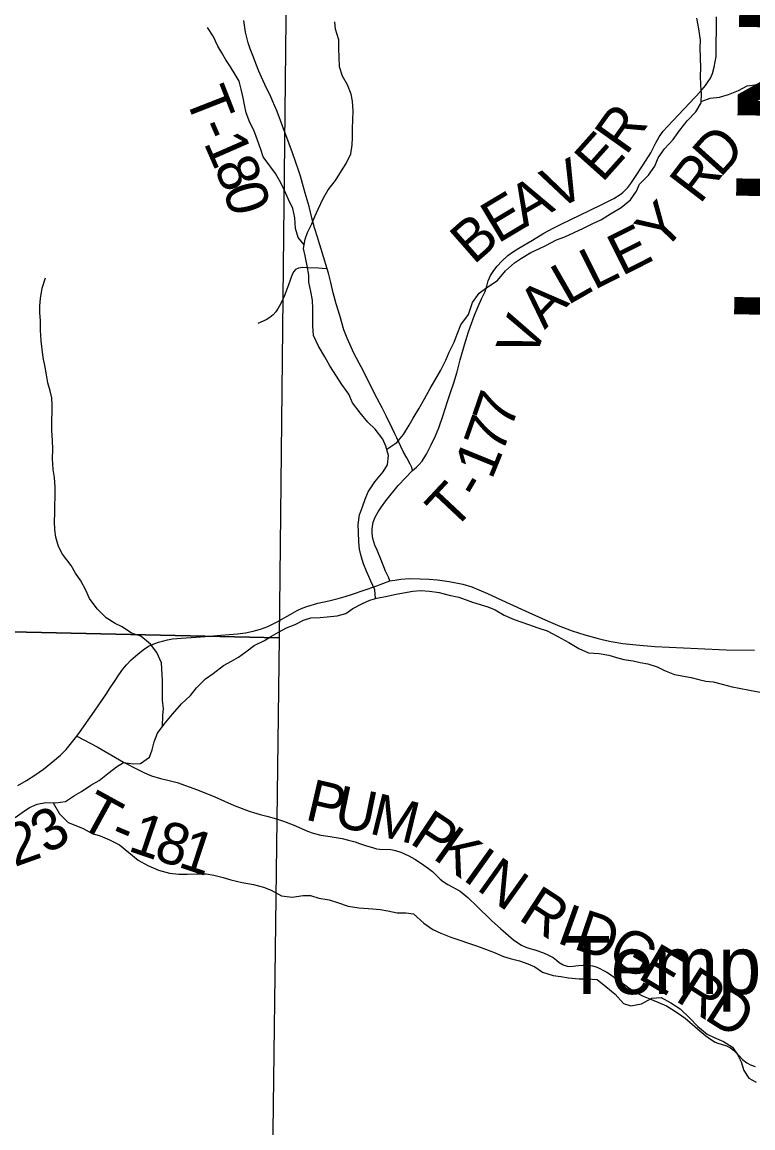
# Model space of a CAD drawing. Extents: x 0 to 191, y 0 to 55.
# Drawn here: x 148.858 to 149.356, y 23.231 to 23.985 of the extents above; entities that cross this region are included whole.
import ezdxf

# ---------------------------------------------------------------- set-up
doc = ezdxf.new("R2010")
doc.units = 0
for name, color, linetype in [('GM_X_Corporation', 7, 'Continuous'), ('GM_X_County_Road', 7, 'Continuous'), ('GM_X_County_Road_Text', 7, 'Continuous'), ('GM_X_County_Text', 7, 'Continuous'), ('GM_X_Minor_River', 7, 'Continuous'), ('GM_X_Township_Road', 7, 'Continuous'), ('GM_X_Township_Road_Text', 7, 'Continuous'), ('GM_X_Unincorporated_Text', 7, 'Continuous')]:
    doc.layers.add(name, color=color, linetype=linetype)

msp = doc.modelspace()

# ---------------------------------------------------------------- linework, layer by layer
at = {"layer": 'GM_X_Corporation'}
for points in [[(148.53297, 24.08032), (149.03882, 24.07143), (149.03316, 23.56525), (148.52633, 23.57659)], [(149.03316, 23.56525), (149.02664, 23.05167), (148.5174, 23.05975), (148.52633, 23.57659)]]:
    msp.add_lwpolyline(points, close=True, dxfattribs=at)
at = {"layer": 'GM_X_County_Road'}
msp.add_lwpolyline([(148.85501, 23.46471), (148.86079, 23.46796), (148.86656, 23.47163), (148.8724, 23.47584), (148.87997, 23.48191), (148.88406, 23.4854), (148.88803, 23.48925), (148.89525, 23.49815), (148.89711, 23.50086), (148.90722, 23.51529), (148.91522, 23.52696), (148.91792, 23.53111), (148.92141, 23.53628), (148.92388, 23.54007), (148.92664, 23.54386), (148.92905, 23.54681), (148.93236, 23.55036), (148.93681, 23.5542), (148.94054, 23.55721), (148.94421, 23.5595), (148.94854, 23.56148), (148.95094, 23.56226), (148.95371, 23.56305), (148.95702, 23.56383), (148.96057, 23.56449), (148.9664, 23.56509), (148.9732, 23.56557), (148.98601, 23.56647), (148.99352, 23.56708), (149.00489, 23.56804), (149.01024, 23.56876), (149.01554, 23.56984), (149.02047, 23.57129), (149.02558, 23.57309), (149.03196, 23.5761), (149.04074, 23.58115), (149.04555, 23.58392), (149.04898, 23.58542), (149.0521, 23.58674), (149.05962, 23.58897), (149.06714, 23.59053), (149.07346, 23.59203), (149.07839, 23.59342), (149.08336, 23.59496), (149.09926, 23.60058), (149.10872, 23.6041), (149.11213, 23.60467), (149.11628, 23.60527), (149.12253, 23.60581), (149.12945, 23.60557), (149.1354, 23.60527), (149.1413, 23.60479), (149.14924, 23.6037), (149.1585, 23.60196), (149.16463, 23.60003), (149.16944, 23.59805), (149.1754, 23.59546), (149.18821, 23.58969), (149.20361, 23.58253), (149.21684, 23.5767), (149.22478, 23.57321), (149.23326, 23.57002), (149.24174, 23.56732), (149.251, 23.56479), (149.25467, 23.56389), (149.25972, 23.56274), (149.26766, 23.56148), (149.27692, 23.56046), (149.28949, 23.55944), (149.31884, 23.55799), (149.33815, 23.55703), (149.35768, 23.55691)], dxfattribs=at)
at = {"layer": 'GM_X_Minor_River'}
for points in [[(149.16255, 23.78571), (149.16521, 23.79378), (149.16967, 23.80029), (149.17492, 23.80414), (149.18223, 23.80897), (149.18764, 23.81549), (149.19381, 23.82088), (149.19868, 23.82416), (149.20507, 23.82803), (149.21033, 23.83056), (149.21522, 23.83271), (149.22255, 23.83659), (149.22819, 23.83875), (149.23459, 23.84149), (149.24098, 23.8446), (149.24681, 23.84752), (149.2532, 23.85044), (149.25939, 23.85431), (149.26653, 23.85857), (149.27308, 23.86377), (149.27717, 23.8697), (149.27919, 23.87466), (149.28535, 23.88061), (149.28963, 23.88674), (149.29182, 23.89245), (149.2961, 23.89857), (149.30207, 23.90509), (149.30672, 23.91141), (149.31174, 23.91773), (149.31753, 23.92387), (149.32124, 23.92999), (149.32153, 23.93644), (149.3209, 23.94174), (149.32081, 23.94856), (149.32094, 23.9535), (149.32066, 23.96089), (149.32058, 23.96753), (149.3207, 23.97265), (149.31966, 23.98041), (149.31824, 23.98779)], [(149.05033, 23.83315), (149.04634, 23.83827), (149.04443, 23.84434), (149.04403, 23.85156), (149.04269, 23.85801), (149.03964, 23.86407), (149.03697, 23.87014), (149.0343, 23.87545), (149.03068, 23.88189), (149.02687, 23.88701), (149.02231, 23.89326), (149.02078, 23.89819), (149.01849, 23.90445), (149.016, 23.91128), (149.01333, 23.91658), (149.01085, 23.92322), (149.0097, 23.92854), (149.00874, 23.93347), (149.0074, 23.93935), (149.00606, 23.94466), (149.0032, 23.9494), (148.99996, 23.95452), (148.99691, 23.95926), (148.99425, 23.964), (148.99139, 23.96874), (148.98815, 23.97537), (148.98434, 23.98144)], [(149.09903, 23.592), (149.0985, 23.59811), (149.09583, 23.60399), (149.09278, 23.61081), (149.09087, 23.61574), (149.08915, 23.62086), (149.08819, 23.62579), (149.08761, 23.63072), (149.0874, 23.63737), (149.0872, 23.64249), (149.08814, 23.64914), (149.09002, 23.65465), (149.09191, 23.65978), (149.09398, 23.66472), (149.09852, 23.67157), (149.1042, 23.67842), (149.10722, 23.68318), (149.10778, 23.68963), (149.10605, 23.69589), (149.10396, 23.70063), (149.09882, 23.70764), (149.09387, 23.71237), (149.08855, 23.71862), (149.08322, 23.72543), (149.08074, 23.7315), (149.07598, 23.73794), (149.07236, 23.74362), (149.06779, 23.75063), (149.06437, 23.75689), (149.06017, 23.76409), (149.05674, 23.77129), (149.05616, 23.77793), (149.05633, 23.78439), (149.05632, 23.78951), (149.05593, 23.7954), (149.05478, 23.80128), (149.05362, 23.80773), (149.05361, 23.81248), (149.05246, 23.81893), (149.05111, 23.82576), (149.04996, 23.83069), (149.0509, 23.83696), (149.05259, 23.84171), (149.05562, 23.84761), (149.05769, 23.85255), (149.05977, 23.85749), (149.06335, 23.86472), (149.06676, 23.87062), (149.07167, 23.87709), (149.07583, 23.88355), (149.07905, 23.88869), (149.08226, 23.89516), (149.083, 23.90143), (149.08337, 23.90617), (149.08335, 23.91244), (149.08353, 23.91852), (149.0837, 23.9244), (149.08331, 23.93124), (149.08235, 23.93598), (149.07987, 23.94224), (149.07644, 23.94812), (149.07453, 23.95457), (149.07413, 23.9614), (149.07393, 23.96672), (149.07391, 23.97299), (149.07181, 23.98019), (149.07123, 23.98513)], [(149.32127, 23.93085), (149.32724, 23.93329), (149.33367, 23.93375), (149.33989, 23.93572), (149.34666, 23.93846), (149.35267, 23.94157), (149.35966, 23.94242)], [(148.95363, 23.50492), (148.95392, 23.51243), (148.9543, 23.51717), (148.95371, 23.52267), (148.95368, 23.53615), (148.9529, 23.5483), (148.94985, 23.55531), (148.94547, 23.56099), (148.93882, 23.56647), (148.93255, 23.56854), (148.92609, 23.5727), (148.92134, 23.57496), (148.91526, 23.57893), (148.90899, 23.58498), (148.90385, 23.59199), (148.90137, 23.59767), (148.89794, 23.60412), (148.89432, 23.60942), (148.89128, 23.61454), (148.88538, 23.6223), (148.88271, 23.62761), (148.8808, 23.63386), (148.88022, 23.63899), (148.88001, 23.64449), (148.88019, 23.65019), (148.88018, 23.65512), (148.88055, 23.66177), (148.88034, 23.66803), (148.87995, 23.67467), (148.87918, 23.67999), (148.87859, 23.6872), (148.87876, 23.69384), (148.87856, 23.69973), (148.87817, 23.70656), (148.87815, 23.71339), (148.87833, 23.71947), (148.87832, 23.72421), (148.87812, 23.72896), (148.87697, 23.7337), (148.87544, 23.73901), (148.87448, 23.74451), (148.87351, 23.74983), (148.87236, 23.75647), (148.87159, 23.76216), (148.87082, 23.76766), (148.87042, 23.77506), (148.87041, 23.78171), (148.87001, 23.78683), (148.87, 23.79158), (148.87037, 23.79652), (148.87168, 23.80374), (148.87375, 23.81077)], [(149.10662, 23.69384), (149.11345, 23.69838), (149.11818, 23.7039), (149.12196, 23.71018), (149.12479, 23.71493), (149.12857, 23.7214), (149.13254, 23.72825), (149.13632, 23.73528), (149.13953, 23.7408), (149.1435, 23.74783), (149.1469, 23.75449), (149.14936, 23.76), (149.15257, 23.76685), (149.15464, 23.77236), (149.15728, 23.77863), (149.16255, 23.78571)], [(148.97684, 23.53129), (148.98309, 23.53738), (148.9882, 23.54101), (148.99521, 23.54634), (149.00071, 23.5494), (149.00544, 23.55207), (149.01056, 23.55569), (149.01624, 23.56008), (149.02325, 23.56351), (149.02799, 23.56638), (149.03292, 23.56924), (149.03822, 23.5721), (149.0441, 23.5744), (149.04997, 23.57727), (149.0549, 23.57899), (149.06135, 23.5792), (149.06609, 23.5796), (149.07292, 23.58019), (149.0788, 23.58191), (149.08354, 23.58534), (149.09017, 23.58878), (149.0951, 23.59089), (149.09984, 23.59223), (149.10704, 23.59377), (149.11197, 23.59493), (149.11804, 23.59589), (149.12449, 23.59705), (149.1298, 23.59745), (149.13587, 23.59709), (149.14233, 23.59616), (149.14916, 23.59429), (149.1558, 23.59298), (149.16526, 23.58961)], [(149.16526, 23.58961), (149.17572, 23.58634), (149.18067, 23.58432), (149.18676, 23.5808), (149.1936, 23.57785), (149.19873, 23.57602), (149.20348, 23.57437), (149.20975, 23.57199), (149.21621, 23.56998), (149.22344, 23.56628), (149.23087, 23.56202), (149.23773, 23.55793), (149.24438, 23.55498), (149.25157, 23.55469), (149.25821, 23.55345), (149.26352, 23.55181), (149.26845, 23.55055), (149.27471, 23.54949), (149.27964, 23.54841), (149.28475, 23.54753), (149.29121, 23.54553), (149.29616, 23.54293), (149.303, 23.54037), (149.31437, 23.53824), (149.31968, 23.53679), (149.32442, 23.53571), (149.32935, 23.53539), (149.33561, 23.53376), (149.34244, 23.53177), (149.34718, 23.53088), (149.35419, 23.52964), (149.36139, 23.52821)], [(148.85315, 23.44283), (148.85788, 23.44626), (148.863, 23.44969), (148.86811, 23.45199), (148.87399, 23.45314), (148.88063, 23.45278), (148.88746, 23.45376), (148.89371, 23.45776), (148.89845, 23.46062), (148.9047, 23.46482), (148.91039, 23.46806), (148.91739, 23.47359), (148.92232, 23.4774), (148.92706, 23.48026), (148.93389, 23.47934), (148.93863, 23.47954), (148.94469, 23.48393), (148.94658, 23.48887), (148.94808, 23.49438), (148.95016, 23.50027), (148.9547, 23.50635), (148.96056, 23.51321), (148.96662, 23.52025), (148.97268, 23.52596), (148.97684, 23.53129)], [(148.87917, 23.45286), (148.8835, 23.44539), (148.8892, 23.43934), (148.89452, 23.43726), (148.89946, 23.43538), (148.90572, 23.4318), (148.91104, 23.4303), (148.9175, 23.42747), (148.92433, 23.42426), (148.93061, 23.41897), (148.93707, 23.41367), (148.94372, 23.41009), (148.95093, 23.40689), (148.95834, 23.40482), (148.96479, 23.40408), (148.97048, 23.4041), (148.97712, 23.40431), (148.98357, 23.40433), (148.9887, 23.40359), (148.99515, 23.4019), (149.00028, 23.4004), (149.00806, 23.39853), (149.01565, 23.39703), (149.02249, 23.39535), (149.0278, 23.39328), (149.03483, 23.38931), (149.04223, 23.38839), (149.04963, 23.38974), (149.05475, 23.38957), (149.06026, 23.38788), (149.06747, 23.38676), (149.07298, 23.38488), (149.08038, 23.38244), (149.08759, 23.38132), (149.09708, 23.38059), (149.10221, 23.38004), (149.10733, 23.3791), (149.11378, 23.3778), (149.11967, 23.37781), (149.12498, 23.37707), (149.13201, 23.37083), (149.13809, 23.36649), (149.1436, 23.36404), (149.15044, 23.36121), (149.16849, 23.3552)], [(149.16849, 23.3552), (149.17957, 23.35098), (149.18623, 23.34803), (149.19097, 23.34658), (149.19723, 23.34514), (149.20293, 23.34294), (149.20769, 23.34091), (149.21283, 23.33738), (149.22024, 23.33519), (149.22535, 23.33431), (149.23066, 23.33343), (149.23785, 23.33276), (149.24334, 23.33283), (149.25015, 23.33235), (149.25626, 23.32769), (149.26257, 23.32246), (149.26832, 23.3159), (149.27325, 23.31444), (149.28042, 23.31586), (149.28756, 23.31974), (149.29399, 23.32001), (149.30046, 23.31649), (149.30694, 23.3124), (149.31326, 23.30623), (149.31901, 23.30024), (149.32531, 23.29501), (149.33007, 23.2928), (149.33653, 23.29003), (149.34263, 23.28632), (149.34609, 23.28124), (149.34843, 23.27616), (149.35039, 23.27031), (149.35367, 23.26504), (149.35862, 23.26245)]]:
    msp.add_lwpolyline(points, dxfattribs=at)
at = {"layer": 'GM_X_Township_Road'}
for points in [[(149.10872, 23.6041), (149.1078, 23.60665), (149.10581, 23.6108), (149.10305, 23.61778), (149.1001, 23.62494), (149.09862, 23.62854), (149.09724, 23.63295), (149.09671, 23.6363), (149.09662, 23.63957), (149.09742, 23.64406), (149.09878, 23.64751), (149.10087, 23.65115), (149.10309, 23.65469), (149.10613, 23.65875), (149.11448, 23.66913), (149.1243, 23.67941), (149.12707, 23.68169), (149.12889, 23.68335), (149.13077, 23.68563), (149.13228, 23.68797), (149.13375, 23.69056), (149.13696, 23.69678), (149.13988, 23.70297), (149.14225, 23.70851), (149.1449, 23.71645), (149.14813, 23.72637), (149.14992, 23.73194), (149.15254, 23.73918), (149.15469, 23.74657), (149.15666, 23.75473), (149.15974, 23.76504), (149.16242, 23.77388), (149.16652, 23.78521), (149.16895, 23.79115), (149.17126, 23.79648), (149.17372, 23.80141), (149.17489, 23.80498), (149.17582, 23.80855), (149.17674, 23.81061), (149.17754, 23.81231), (149.1797, 23.81579), (149.18204, 23.81868), (149.18521, 23.82213), (149.1894, 23.82595), (149.19318, 23.82857), (149.19685, 23.831), (149.20602, 23.83639), (149.21387, 23.8411), (149.22028, 23.84464), (149.22567, 23.84732), (149.23842, 23.85335), (149.25298, 23.86053), (149.26154, 23.86478), (149.26594, 23.86758), (149.26785, 23.86897), (149.26936, 23.87035), (149.27118, 23.87232), (149.27315, 23.87491), (149.27589, 23.87916), (149.28155, 23.88775), (149.28685, 23.89597), (149.2903, 23.90284), (149.29255, 23.90678), (149.29532, 23.9106), (149.29834, 23.91392), (149.32066, 23.93766), (149.32405, 23.94173), (149.32608, 23.94453), (149.3275, 23.9469), (149.32885, 23.95007), (149.32999, 23.95423), (149.33134, 23.96168), (149.33173, 23.98861)], [(149.1243, 23.67941), (149.12372, 23.68141), (149.12255, 23.68372), (149.1203, 23.68794), (149.11814, 23.69179), (149.11629, 23.6958), (149.11498, 23.69875), (149.11352, 23.7017), (149.11227, 23.70432), (149.11031, 23.70829), (149.10646, 23.71627), (149.10351, 23.72205), (149.10024, 23.7284), (149.09556, 23.7373), (149.09163, 23.7452), (149.08912, 23.74997), (149.08778, 23.75262), (149.08415, 23.75944), (149.07962, 23.76951), (149.07745, 23.77529), (149.07456, 23.78503), (149.07223, 23.79289), (149.07021, 23.80049), (149.06851, 23.80749), (149.06684, 23.81393), (149.06612, 23.81682), (149.0635, 23.82507), (149.05933, 23.83839), (149.05737, 23.84482), (149.05546, 23.85155), (149.05364, 23.8593), (149.05111, 23.86833), (149.04792, 23.88001), (149.04646, 23.88421), (149.04235, 23.896), (149.04, 23.90211), (149.0358, 23.9137), (149.0318, 23.9241), (149.02865, 23.93146), (149.02704, 23.93518), (149.02474, 23.93995), (149.02123, 23.94742), (149.0195, 23.95154), (149.01733, 23.95684), (149.01578, 23.96107), (149.01357, 23.9667), (149.01208, 23.97099), (149.01114, 23.97444), (149.01041, 23.97817), (149.00925, 23.98606)], [(149.06612, 23.81682), (149.0627, 23.81715), (149.06008, 23.81723), (149.05295, 23.81755), (149.04912, 23.81763), (149.04652, 23.81727), (149.04445, 23.81643), (149.04325, 23.81499), (149.04225, 23.81296), (149.04109, 23.80968), (149.03938, 23.80533), (149.0369, 23.7987), (149.03447, 23.79316), (149.03263, 23.78992), (149.03095, 23.78741), (149.02916, 23.78553), (149.02696, 23.78357), (149.02446, 23.78203), (149.01862, 23.77967)], [(148.89525, 23.49815), (148.90902, 23.49105), (148.92706, 23.48063), (148.93688, 23.47552), (148.94096, 23.47338), (148.94342, 23.47231), (148.94607, 23.47124), (148.95233, 23.46942), (148.95724, 23.46819), (148.96362, 23.46657), (148.97753, 23.46166), (148.98929, 23.4569), (149.00264, 23.45092), (149.0127, 23.44716), (149.01587, 23.44613), (149.02025, 23.44489), (149.02483, 23.44375), (149.03144, 23.44193), (149.03631, 23.44023), (149.04273, 23.43769), (149.05256, 23.43357), (149.05652, 23.43218), (149.06175, 23.4308), (149.06816, 23.42989), (149.07621, 23.42846), (149.0806, 23.42743), (149.08512, 23.4262), (149.08817, 23.42513), (149.09225, 23.42363), (149.09768, 23.42204), (149.09966, 23.42153), (149.10204, 23.42125), (149.10936, 23.42109), (149.11257, 23.42034), (149.11634, 23.41915), (149.12168, 23.41669), (149.12576, 23.4144), (149.12909, 23.41234), (149.13198, 23.41039), (149.13519, 23.40814), (149.13789, 23.406), (149.14007, 23.40374), (149.14304, 23.40069), (149.1451, 23.39906), (149.14827, 23.39704), (149.15674, 23.39253), (149.16193, 23.38825), (149.16819, 23.38231), (149.1781, 23.37248), (149.18447, 23.36698), (149.19315, 23.35937), (149.196, 23.35735), (149.1987, 23.35581), (149.20147, 23.3545), (149.20428, 23.35355), (149.20765, 23.35256), (149.21367, 23.35046), (149.21712, 23.34903), (149.22029, 23.34729), (149.22239, 23.34551), (149.22433, 23.34392), (149.22714, 23.34234), (149.22975, 23.34139), (149.23154, 23.34123), (149.23391, 23.34139), (149.2374, 23.34194), (149.24065, 23.34222), (149.24382, 23.34214), (149.24711, 23.34158), (149.24948, 23.34091), (149.25202, 23.33988), (149.25451, 23.33861), (149.25681, 23.33738), (149.25875, 23.3362), (149.26212, 23.33378), (149.26917, 23.32867), (149.27266, 23.32601), (149.27698, 23.32328), (149.28157, 23.3209), (149.28732, 23.31869), (149.29754, 23.31449), (149.30126, 23.31223), (149.30582, 23.30918), (149.31017, 23.30597), (149.31695, 23.30026), (149.32027, 23.29745), (149.32447, 23.29401), (149.32764, 23.29159), (149.33081, 23.28965), (149.33267, 23.2889), (149.33473, 23.28822), (149.33842, 23.28711), (149.34123, 23.28581), (149.34329, 23.28422), (149.34709, 23.28022), (149.34931, 23.27772), (149.35232, 23.27547), (149.35494, 23.2742), (149.35799, 23.27301)]]:
    msp.add_lwpolyline(points, dxfattribs=at)

# ---------------------------------------------------------------- texts
at = {"layer": 'GM_X_County_Road_Text'}
for s, rotation, p in [('3', 30.58969, (148.87459, 23.41731)), ('2', 19.54843, (148.85269, 23.40893))]:
    msp.add_text(s, height=0.02841, rotation=rotation, dxfattribs=at).set_placement(p)
at = {"layer": 'GM_X_County_Text'}
msp.add_text('NOBLE COUNTY', height=0.094697, rotation=269.02137, dxfattribs=at).set_placement((149.3601, 24.74846))
at = {"layer": 'GM_X_Township_Road_Text'}
for s, rotation, p in [('T', 291.35814, (148.96866, 23.93438)), ('R', 54.60317, (149.26997, 23.89352)), ('-', 293.44443, (148.97683, 23.91355)), ('D', 48.03309, (149.33412, 23.87833)), ('1', 293.58986, (148.9815, 23.90277)), ('E', 48.20735, (149.25365, 23.87497)), ('8', 292.33967, (148.98844, 23.88688)), ('V', 26.23596, (149.22181, 23.85677)), ('R', 52.65081, (149.32035, 23.86025)), ('0', 286.29852, (148.99483, 23.87144)), ('A', 29.78102, (149.20052, 23.84457)), ('E', 30.9101, (149.18242, 23.83373)), ('Y', 46.39573, (149.29462, 23.82755)), ('B', 41.24393, (149.16597, 23.81914)), ('E', 26.64554, (149.26707, 23.81169)), ('L', 26.80462, (149.24812, 23.80212)), ('L', 29.88255, (149.23005, 23.79172)), ('A', 46.27257, (149.21446, 23.77498)), ('V', 69.57526, (149.20734, 23.75412)), ('7', 71.01664, (149.19139, 23.70677)), ('7', 70.36427, (149.18539, 23.68995)), ('1', 67.82298, (149.1783, 23.67246)), ('T', 46.81243, (149.15176, 23.6374)), ('-', 59.62964, (149.17044, 23.65843)), ('P', 346.89035, (149.05018, 23.44157)), ('T', 331.24385, (148.89497, 23.4373)), ('U', 348.43361, (149.06966, 23.43704)), ('M', 346.21878, (149.09387, 23.43209)), ('1', 341.19966, (148.92927, 23.42038)), ('P', 326.46939, (149.12146, 23.42578)), ('-', 337.11725, (148.91646, 23.4257)), ('8', 343.19898, (148.94686, 23.41441)), ('K', 324.52839, (149.13723, 23.41534)), ('1', 341.73291, (148.96343, 23.40941)), ('I', 324.4714, (149.15758, 23.40084)), ('N', 324.47393, (149.16707, 23.39406)), ('R', 326.88465, (149.19562, 23.37371)), ('I', 340.17009, (149.22159, 23.35777)), ('D', 341.46553, (149.23323, 23.35358)), ('G', 329.68719, (149.25553, 23.34627)), ('E', 329.2222, (149.27706, 23.33368)), ('R', 327.64794, (149.30264, 23.3184)), ('D', 327.52043, (149.32234, 23.30592))]:
    msp.add_text(s, height=0.02841, rotation=rotation, dxfattribs=at).set_placement(p)
at = {"layer": 'GM_X_Unincorporated_Text'}
msp.add_text('Temperanceville', height=0.0394886, rotation=0.00001, dxfattribs=at).set_placement((149.22724, 23.32244))

doc.saveas('drawing.dxf')
